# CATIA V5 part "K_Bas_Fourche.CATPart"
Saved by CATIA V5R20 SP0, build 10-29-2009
Part number: Bas_Fourche
Bounding box of the stored display mesh (mm): x -110 to 269.975, y -190 to 50, z 0 to 214.714
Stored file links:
  G:\Khaled_CFAO_2011\ST2M\ST2M_GR1\bmartinez\Khaled\CAD_ThinkMOTION\K_Bas_Fourche.CATPart
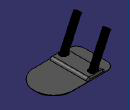
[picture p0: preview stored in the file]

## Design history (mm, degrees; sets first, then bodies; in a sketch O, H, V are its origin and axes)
Body1 (main body)
  Sketch1 on xy-plane, origin (0, 0, 0), H (1, 0, 0), V (0, 1, 0)
    line L1 (150, 50) -> (-60, 50)
    arc A1 centre (-60, 0) radius 50 from (-60, 50) to (-110, 0) ccw
    point P4 (-110, 0)
    line L2 (-110, 0) -> (-110, -140)
    arc A2 centre (-60, -140) radius 50 from (-110, -140) to (-60, -190) ccw
    line L3 (-60, -190) -> (150, -190)
    arc A3 centre (150, -70) radius 120 from (150, -190) to (150, 50) ccw
    distance L1 L3 = 240
    length L1 = 210
    horizontal: L1 H
    coincidence: P4 H
    tangency: A1 L1, L2 A1, A2 L2, L3 A2, A3 L1, A3 L3
  Pad1: profile Sketch1, direction (0, 0, 1), length 10
  Chamfer1: length 8, angle 45, on start face of Pad1
  Sketch2 on end face of Pad1, origin (0, 0, 10), H (1, 0, 0), V (0, 1, 0)
    line L1 (-50, 50) -> (60, 50)
    line L2 (60, 50) -> (60, -190)
    line L3 (60, -190) -> (-50, -190)
    line L4 (-50, -190) -> (-50, 50)
    horizontal: L1 H, L3 H
    vertical: L2 V, L4 V
  Pad2: profile Sketch2, direction (0, 0, 1), length 15
  Fillet1: radius 15, on edge [face of Pad2 from Sketch2.L2 | end face of Pad2]; edge [face of Pad2 from Sketch2.L4 | end face of Pad2]
  Chamfer2: length 8, angle 45, on edge [face of Pad2 | end face of Pad2]; edge [face of Pad2 | face of Fillet1] (x2)
  Chamfer3: length 8, angle 45, on edge [face of Pad2 | end face of Pad2]; edge [face of Pad2 | face of Fillet1] (x2)
  Point1: type OnPlane, Support end face of Pad2, RefPoint vertex [face of Chamfer2 | face of Pad2 | end face of Pad1], H 40, V 30, Direction (1, 0, 0)
  Point2: type OnPlane, Support end face of Pad2, RefPoint vertex [face of Chamfer2 | face of Pad2 | end face of Pad1], H 40, V 210, Direction (1, 0, 0)
  Line1: type PtPt, FirstPoint Point1, SecondPoint Point2
  Plane1: type Angle, RefPlane end face of Pad2, Direction Line1, Angle -25
  Sketch3 on Plane1, origin (19.3009, 0, 34.9328), H (0, -1, 0), V (-0.9063, 0, -0.4226)
    circle A1 centre (160, 23.5029) radius 20
    point P1 (160, 23.5029)
    reference projected point E1 (160, 23.5029) from Point1
    circle A2 centre (-20, 23.5029) radius 20
    point P2 (-20, 23.5029)
    reference projected point E2 (-20, 23.5029) from Point2
    radius A1 = 20
    radius A2 = 20
    coincidence: P1 E1, P2 E2
  Pad3: profile Sketch3, direction (-0.4226, 0, 0.9063), length 200
  Pad4: profile start face of Pad3, direction along Plane1, length 10
  Pad5: profile start face of Pad3, direction along Plane1, length 10
  Sketch4 on end face of Pad3, origin (-94.4564, 0, 202.5624), H (0, -1, 0), V (0.9063, 0, 0.4226)
    circle A1 centre (160, 8.7528) radius 17.55
    point P1 (160, 8.7528)
    circle A2 centre (-20, 8.7528) radius 17.55
    point P2 (-20, 8.7528)
    reference projected point E1 (160, 8.7528) from Point1
    reference projected point E2 (-20, 8.7528) from Point2
    radius A1 = 17.55
    radius A2 = 17.55
    coincidence: E1 P1, E2 P2
  Pocket1: profile Sketch4, direction (0.4226, 0, -0.9063), length 250
  Fillet2: radius 3, on edge [face of Pad4 | end face of Pad2]; edge [face of Pad3 from Sketch3.A1 | end face of Pad2]; edge [face of Pad5 | end face of Pad2]; edge [face of Pad3 from Sketch3.A2 | end face of Pad2]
